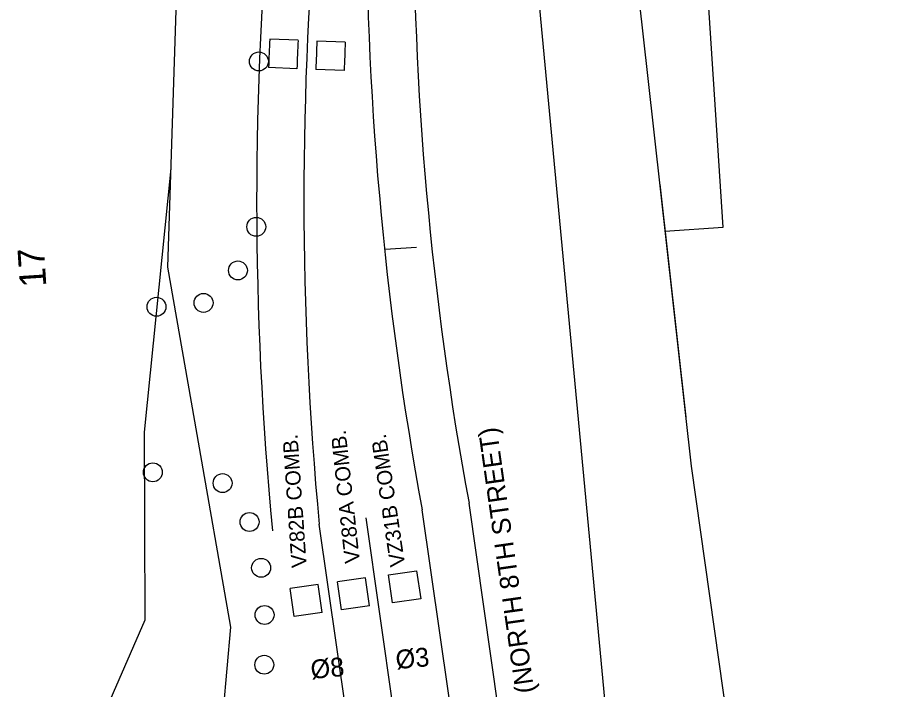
# Model space of a CAD drawing. Extents: x 0 to 1361828, y 0 to 1470398.
# Drawn here: x 686157.7 to 686343.6, y 734957.2 to 735099.3 of the extents above; entities that cross this region are included whole.
import ezdxf

# ---------------------------------------------------------------- set-up
doc = ezdxf.new("R2010")
doc.units = 0
for name, color, linetype in [('$', 7, 'Continuous'), ('BASE', 7, 'Continuous'), ('MOT Stage 1', 7, 'Continuous'), ('MOT Stage 1 Lanes', 7, 'Continuous'), ('R_Horz Alg Station', 7, 'Continuous'), ('R_TYPE_A_CURB', 7, 'Continuous'), ('RW-EX', 7, 'Continuous'), ('RW-PR', 7, 'Continuous'), ('SIGNAL-PR$', 7, 'Continuous'), ('TITEXT', 7, 'Continuous'), ('Video-Zones-pr', 7, 'Continuous')]:
    doc.layers.add(name, color=color, linetype=linetype)

# ---------------------------------------------------------------- blocks, each defined once
blk = doc.blocks.new('BAREL_1796')
at = {"layer": 'MOT Stage 1'}
blk.add_circle((0, 0.01), 2.88, dxfattribs=at)
blk = doc.blocks.new('BAREL_1797')
at = {"layer": 'MOT Stage 1'}
blk.add_circle((0, 0.01), 2.88, dxfattribs=at)
blk = doc.blocks.new('BAREL_1798')
at = {"layer": 'MOT Stage 1'}
blk.add_circle((0, 0.01), 2.88, dxfattribs=at)
blk = doc.blocks.new('BAREL_1799')
at = {"layer": 'MOT Stage 1'}
blk.add_circle((0, 0.01), 2.88, dxfattribs=at)
blk = doc.blocks.new('BAREL_1800')
at = {"layer": 'MOT Stage 1'}
blk.add_circle((0, 0.01), 2.88, dxfattribs=at)
blk = doc.blocks.new('BAREL_1839')
at = {"layer": 'MOT Stage 1'}
blk.add_circle((0, 0.01), 2.88, dxfattribs=at)
blk = doc.blocks.new('BAREL_1840')
at = {"layer": 'MOT Stage 1'}
blk.add_circle((0, 0.01), 2.88, dxfattribs=at)
blk = doc.blocks.new('BAREL_1841')
at = {"layer": 'MOT Stage 1'}
blk.add_circle((0, 0.01), 2.88, dxfattribs=at)
blk = doc.blocks.new('BAREL_1853')
at = {"layer": 'MOT Stage 1'}
blk.add_circle((0, 0.01), 2.88, dxfattribs=at)
blk = doc.blocks.new('BAREL_1854')
at = {"layer": 'MOT Stage 1'}
blk.add_circle((0, 0.01), 2.88, dxfattribs=at)
blk = doc.blocks.new('BAREL_1855')
at = {"layer": 'MOT Stage 1'}
blk.add_circle((0, 0.01), 2.88, dxfattribs=at)

msp = doc.modelspace()

# ---------------------------------------------------------------- linework, layer by layer
at = {"layer": 'MOT Stage 1 Lanes'}
for p, q in [((686267.87, 734894.04), (686253.16, 734996.59)), ((686246.09, 734890.99), (686231.37, 734993.54)), ((686236.18, 734889.6), (686221.47, 734992.16))]:
    msp.add_line(p, q, dxfattribs=at)
msp.add_lwpolyline([(686220.78, 734886.44), (686258.11, 734891.66), (686243.25, 734995.2)], dxfattribs=at)
for centre, radius, start, end in [((686946.79, 735060.88), 738.56, 174.64944, 185.44699), ((686946.77, 735060.88), 728.55, 174.61469, 185.41281), ((686944.02, 735124.57), 712.61, 179.66251, 190.45935), ((686944, 735124.56), 702.6, 179.69727, 190.49468)]:
    msp.add_arc(centre, radius, start, end, dxfattribs=at)
at = {"layer": 'R_Horz Alg Station'}
msp.add_lwpolyline([(686235.41, 735050.33), (686242.06, 735050.76)], dxfattribs=at)
at = {"layer": 'R_TYPE_A_CURB'}
msp.add_line((686293.49, 735064.12), (686299.02, 735014.79), dxfattribs=at)
at = {"layer": 'RW-EX'}
for p, q in [((686282.11, 734952.68), (686263.01, 735155.56)), ((686197.65, 734912.58), (686202.76, 734970.41))]:
    msp.add_line(p, q, dxfattribs=at)
for points in [[(686189.41, 735046.56), (686193.04, 735157.41), (686193.09, 735158.93), (686193.31, 735163.53)], [(686202.76, 734970.41), (686195.62, 735011.12), (686189.41, 735046.56)]]:
    msp.add_lwpolyline(points, dxfattribs=at)
at = {"layer": 'RW-PR'}
for p, q in [((686306.92, 735054.97), (686303.36, 735109.86)), ((686294.61, 735054.18), (686306.92, 735054.97))]:
    msp.add_line(p, q, dxfattribs=at)
for points in [[(686265.32, 735307.32), (686274.84, 735258.53), (686278.78, 735195.38), (686290.99, 735086.46), (686300.18, 735004.43), (686311.76, 734922.2), (686343.56, 734897.83)], [(686190.09, 735067.43), (686184.47, 735011.66), (686184.55, 734971.87), (686160.19, 734915.9)]]:
    msp.add_lwpolyline(points, dxfattribs=at)
at = {"layer": 'Video-Zones-pr'}
for p, q in [((686231.26, 734980.8), (686225.31, 734979.97)), ((686232.13, 734974.87), (686231.26, 734980.8)), ((686221.24, 734979.4), (686215.3, 734978.57)), ((686216.18, 734972.63), (686215.3, 734978.57)), ((686222.12, 734973.46), (686221.24, 734979.4)), ((686226.19, 734974.03), (686225.31, 734979.97)), ((686232.13, 734974.87), (686226.19, 734974.03)), ((686222.12, 734973.46), (686216.18, 734972.63))]:
    msp.add_line(p, q, dxfattribs=at)
for points in [[(686217, 735094.52), (686211, 735094.74)], [(686226.99, 735094.14), (686220.99, 735094.36)], [(686216.74, 735088.52), (686210.75, 735088.75)], [(686226.74, 735088.14), (686220.74, 735088.37)]]:
    msp.add_lwpolyline(points, dxfattribs=at)
msp.add_lwpolyline([(686242.93, 734976.38), (686236.99, 734975.54), (686236.11, 734981.48), (686242.05, 734982.31)], close=True, dxfattribs=at)
for radius, start in [(736.55, 177.36489), (730.55, 177.36105), (726.55, 177.35846), (720.55, 177.35452)]:
    msp.add_arc((686946.77, 735060.88), radius, start, 177.83163, dxfattribs=at)

# ---------------------------------------------------------------- block references
at = {"layer": 'MOT Stage 1', "xscale": 0.6945420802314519, "yscale": 0.6945420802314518, "rotation": 87.04179557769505}
for name, p in [('BAREL_1841', (686208.72, 735090.06)), ('BAREL_1840', (686208.16, 735055.07)), ('BAREL_1839', (686204.28, 735045.85)), ('BAREL_1799', (686187.05, 735038.16)), ('BAREL_1800', (686197.01, 735038.98)), ('BAREL_1798', (686186.28, 735003.15)), ('BAREL_1797', (686201.04, 735000.86)), ('BAREL_1796', (686206.74, 734992.64)), ('BAREL_1853', (686209.18, 734982.95)), ('BAREL_1854', (686209.92, 734972.97)), ('BAREL_1855', (686209.85, 734962.45))]:
    msp.add_blockref(name, p, dxfattribs=at)

# ---------------------------------------------------------------- texts
at = {"layer": '$'}
msp.add_text('17', height=5.6, rotation=93.7158, dxfattribs=at).set_placement((686163.76, 735042.47))
at = {"layer": 'BASE'}
msp.add_text('HWY. 94 (NORTH 8TH STREET)', height=4, rotation=98.1027, dxfattribs=at).set_placement((686270.23, 734934.02))
at = {"layer": 'SIGNAL-PR$'}
for s, rotation, p in [('VZ82A COMB.', 96.1971, (686230.1, 734984.07)), ('VZ82B COMB.', 93.9999, (686218.84, 734983.07)), ('VZ31B COMB.', 98.422, (686239.67, 734983.43))]:
    msp.add_text(s, height=3.2, rotation=rotation, dxfattribs=at).set_placement(p)
at = {"layer": 'TITEXT'}
for s, p in [('%%C3', (686237.81, 734961.5)), ('%%C8', (686219.83, 734959.42))]:
    msp.add_text(s, height=4, rotation=5.4036, dxfattribs=at).set_placement(p)

doc.saveas('drawing.dxf')
